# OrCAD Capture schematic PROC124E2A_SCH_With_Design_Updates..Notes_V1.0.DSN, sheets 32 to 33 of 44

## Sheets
32 31. PRU HEADER: size C; title: PRU HEADER
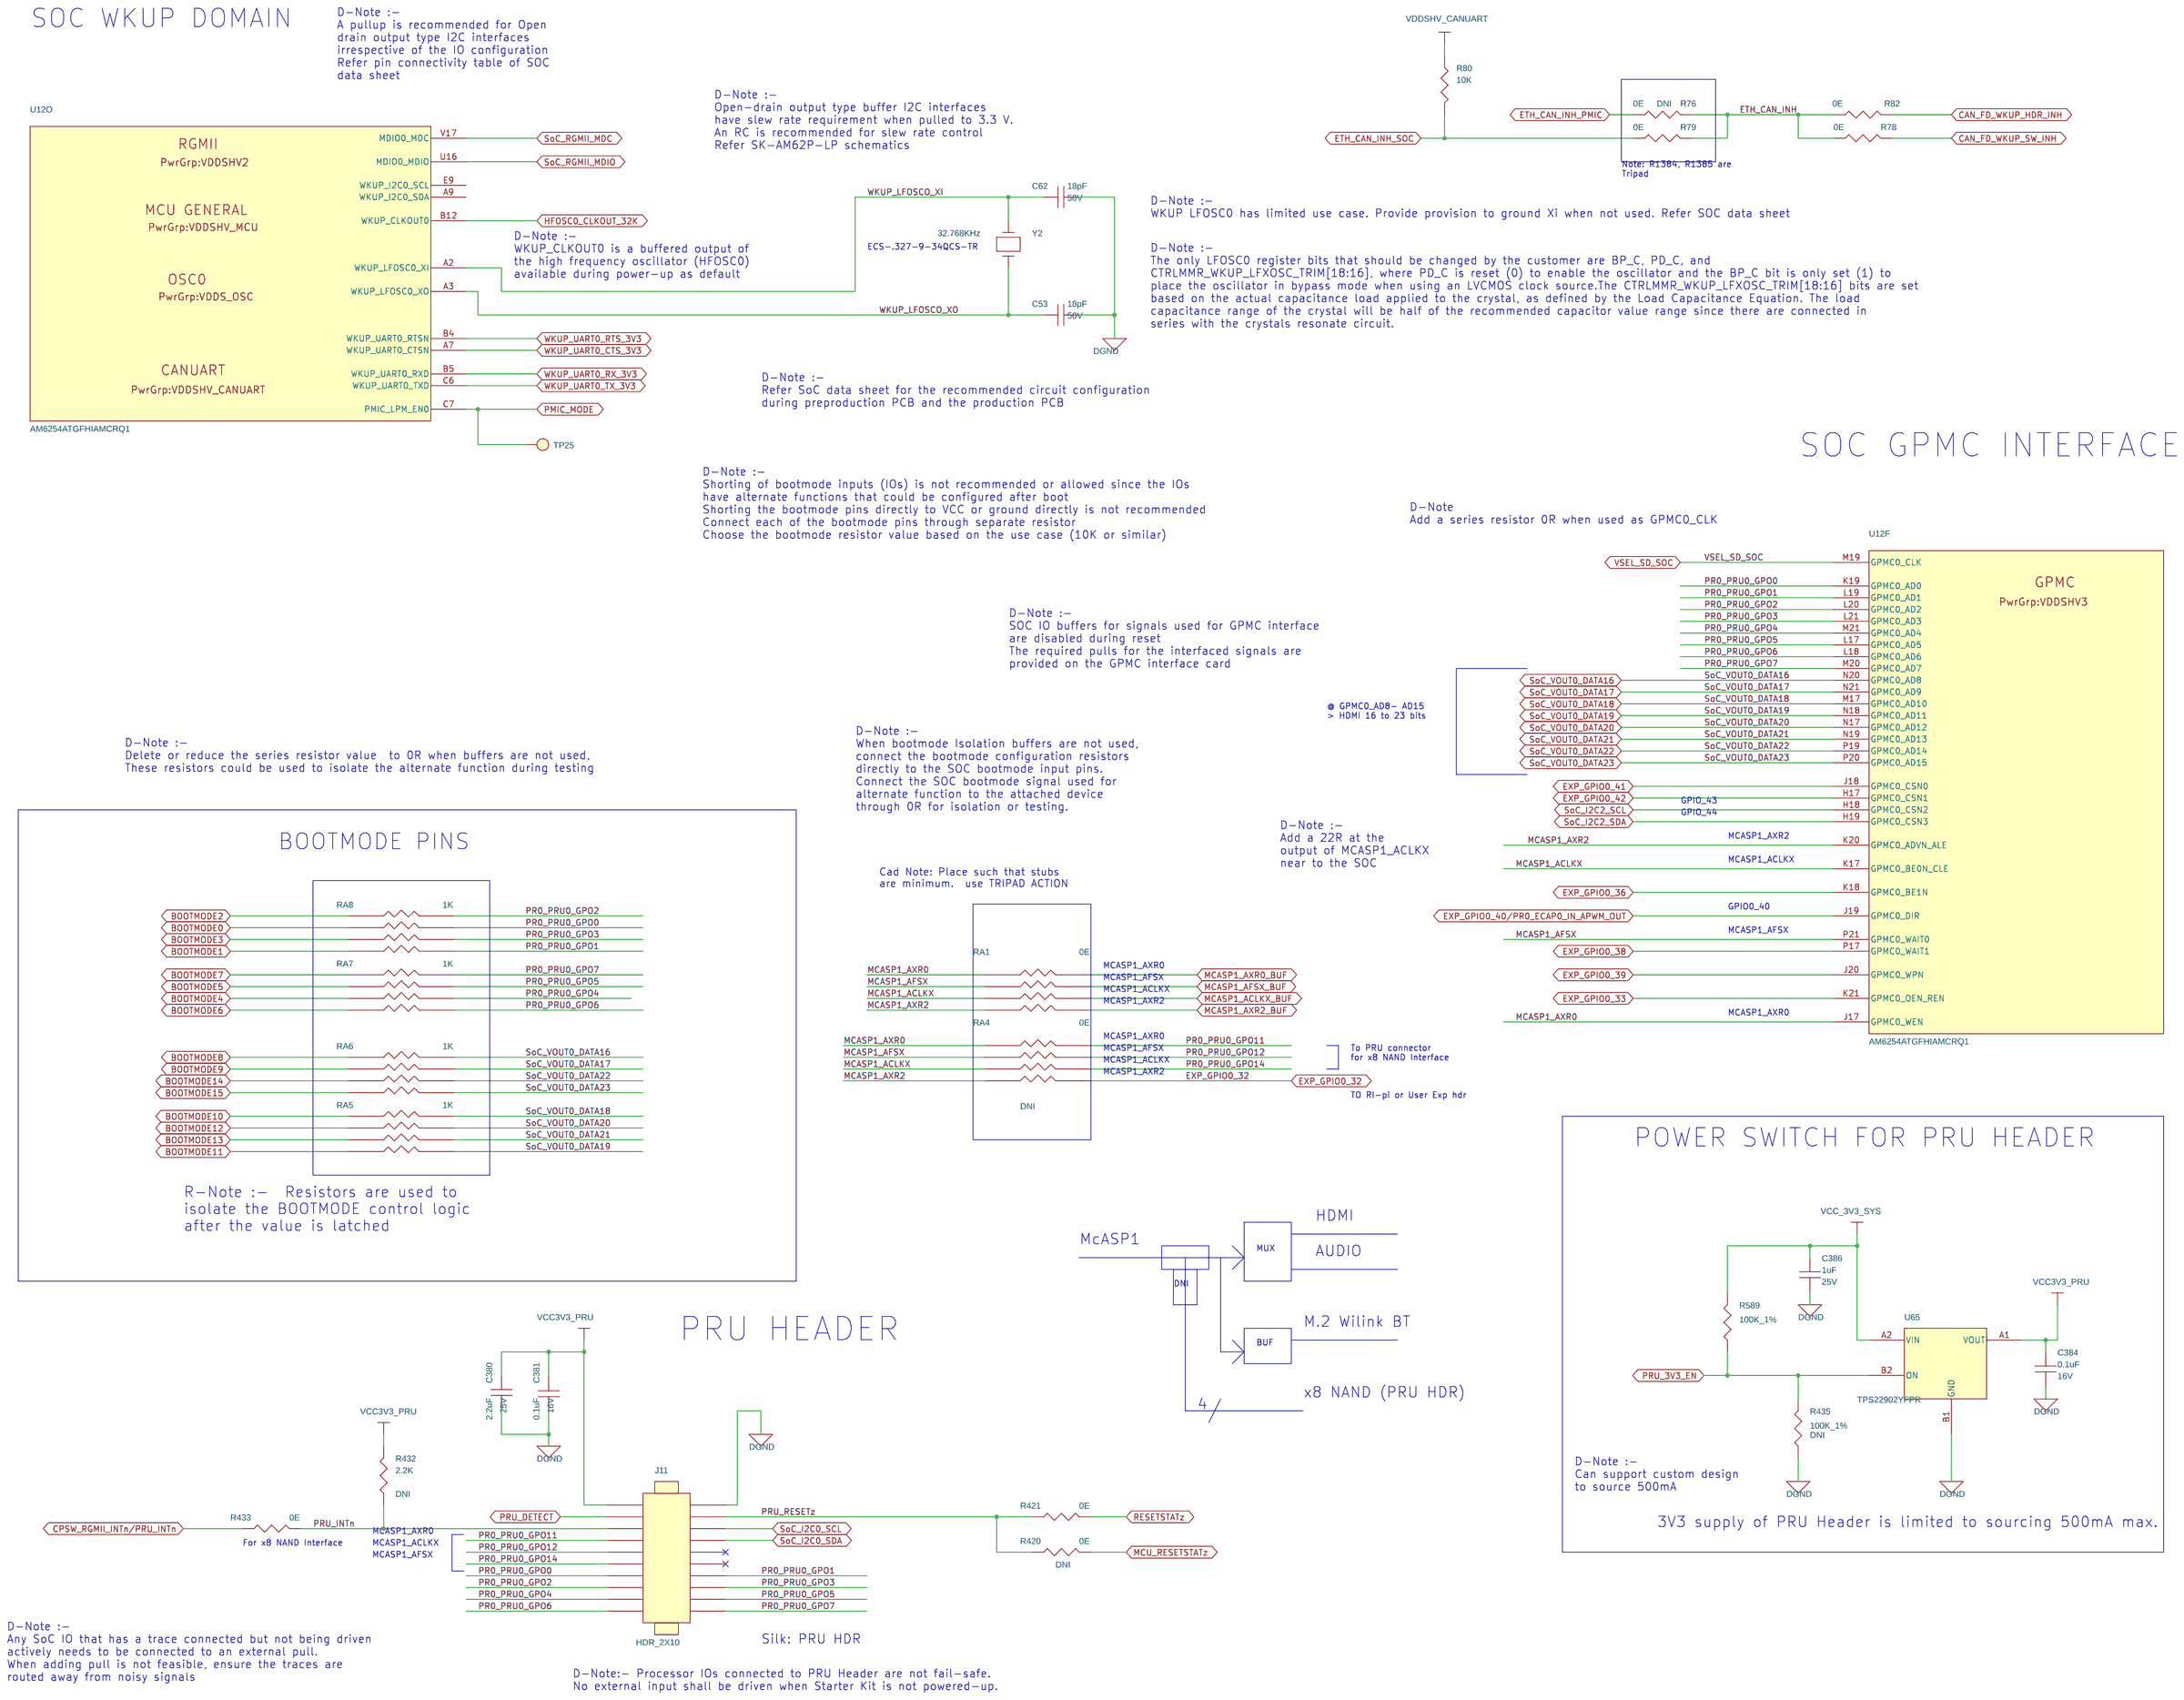
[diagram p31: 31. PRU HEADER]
33 32. USER EXPANSION CONNECTOR: size C; title: USER EXPANSION CONNECTOR
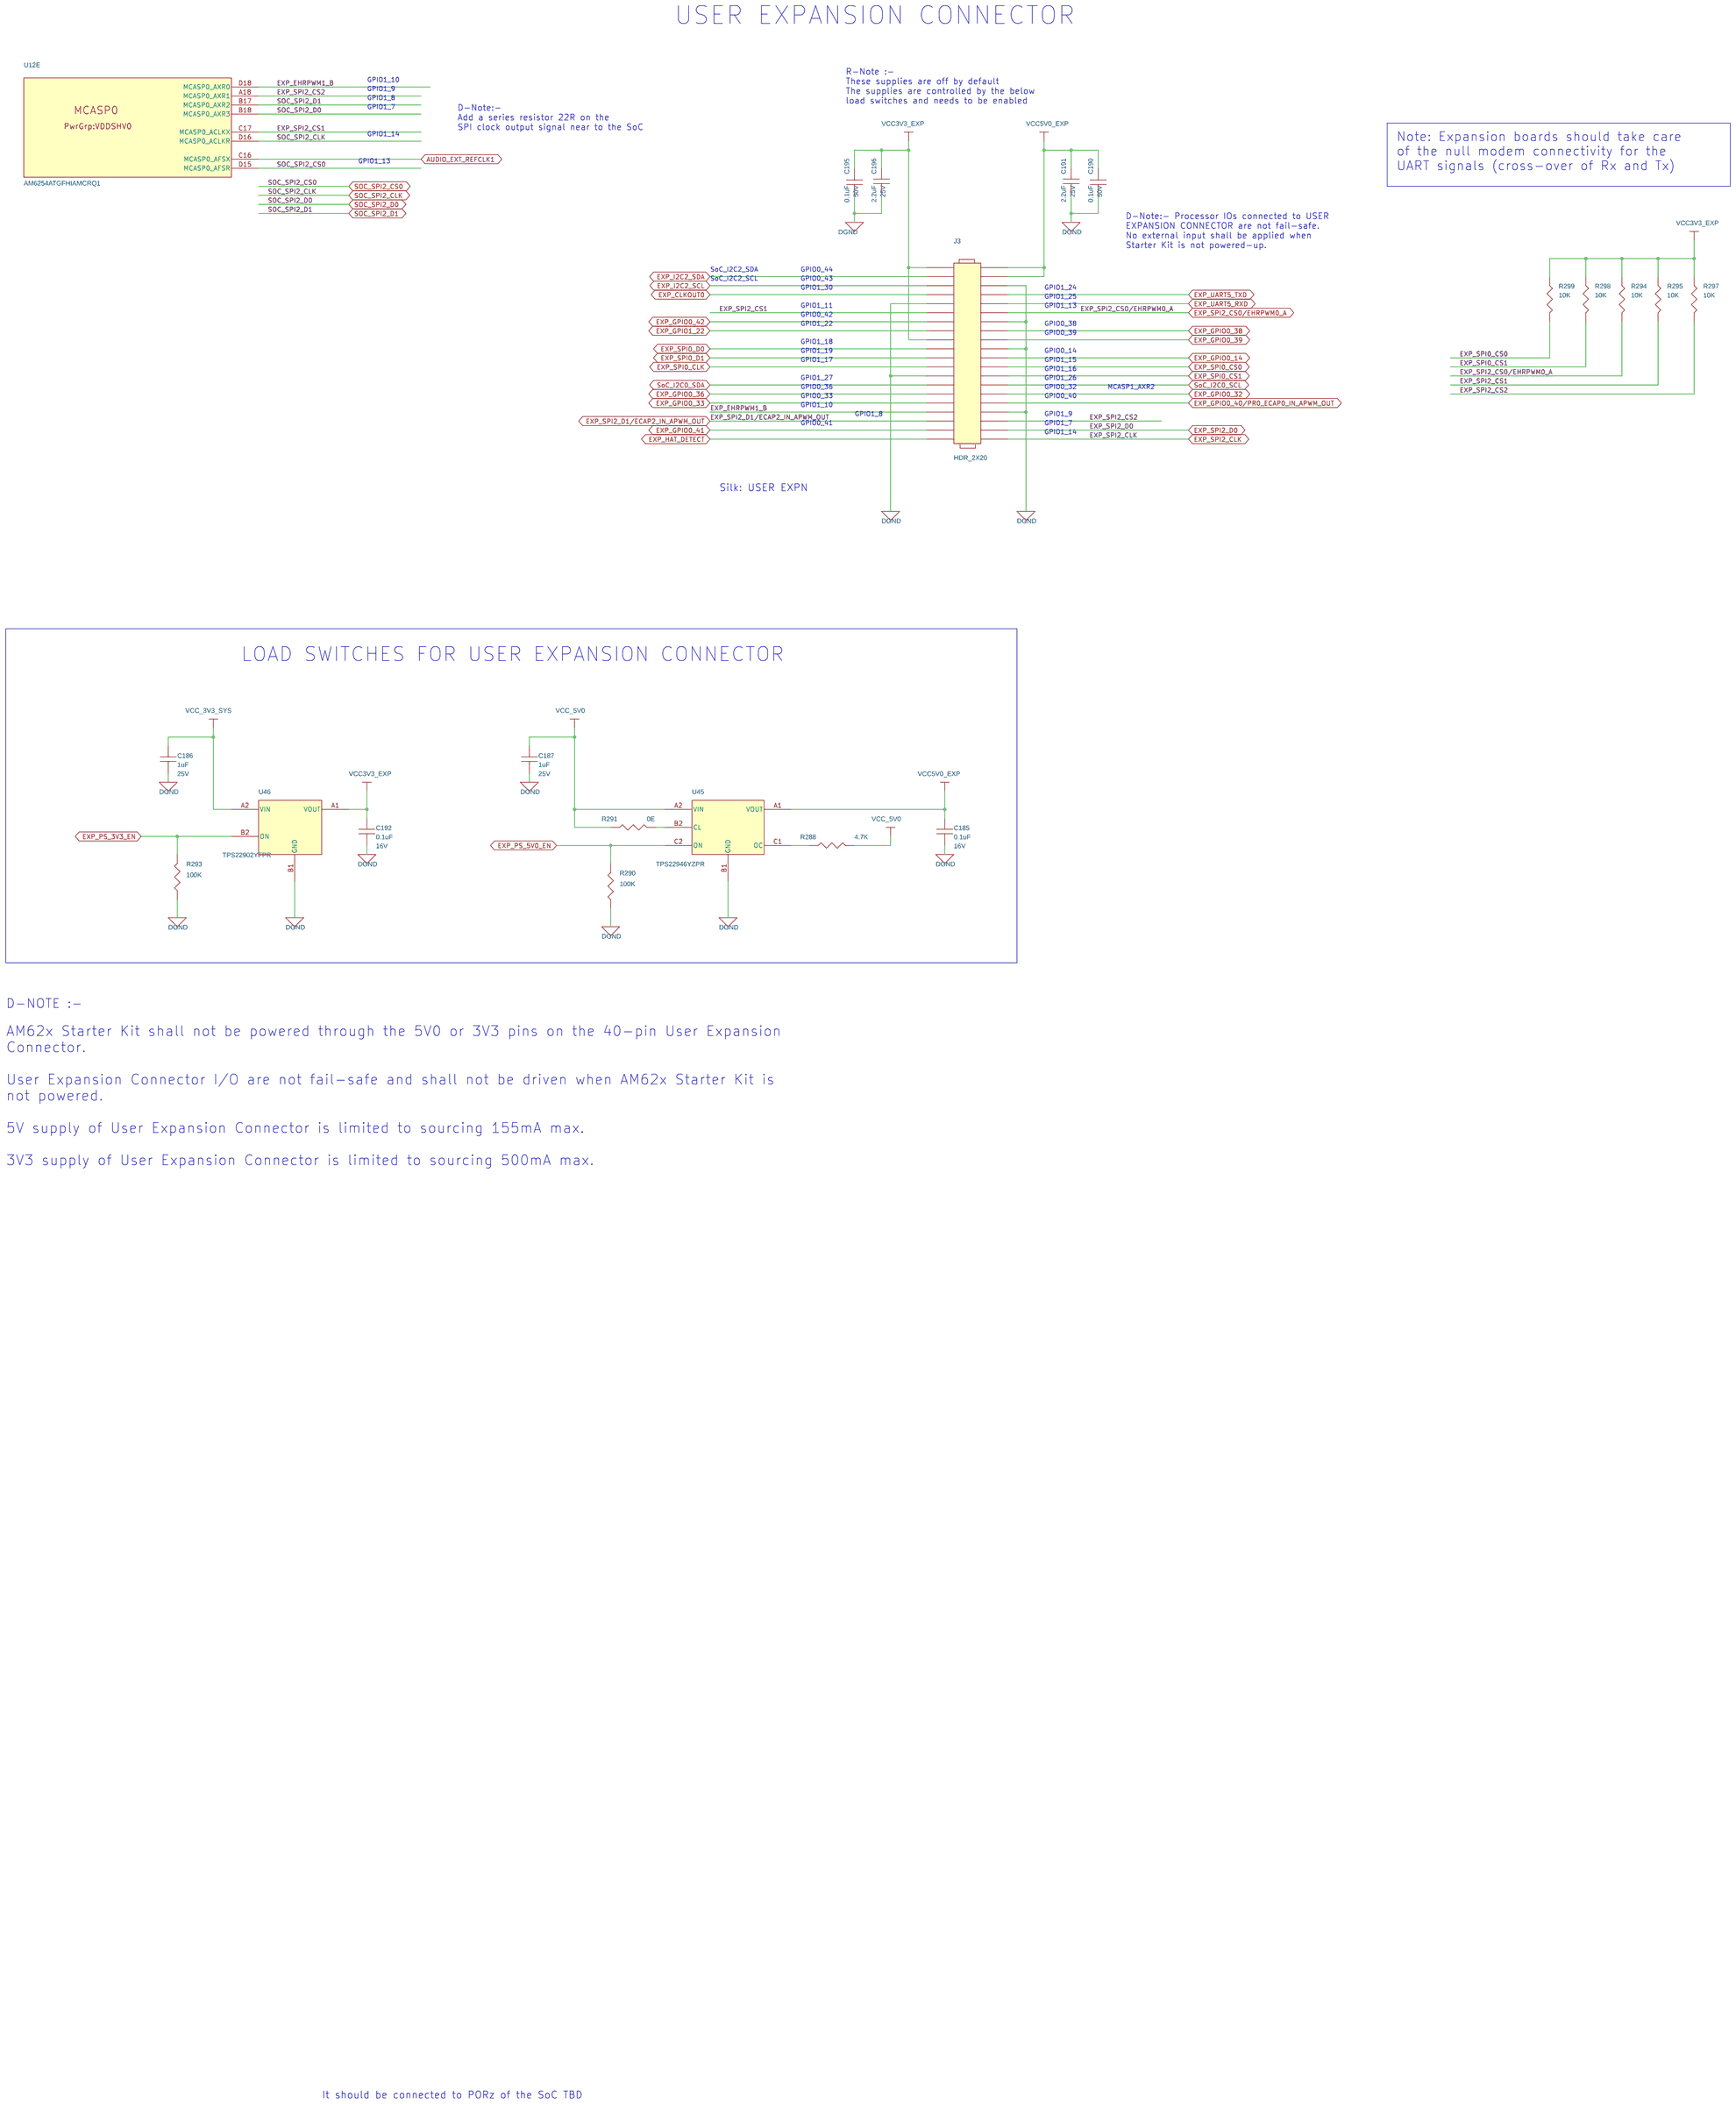
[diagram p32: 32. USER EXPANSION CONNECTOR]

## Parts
sheet 15. SOC POWER CAPS
U12  AM6254ATGFHIAMCRQ1  [FCBGA441_31-49_680X680_2-6]  (sections A,B,C,D,E,F,G,H,I,J,K,L,M,N,O,P,Q,R)
sheet 31. PRU HEADER
C53  18pF  [CAP0402_0-75]
C62  18pF  [CAP0402_0-75]
C380  2.2uF  [CAP0402_0-75]
C381  0.1uF  [CAP0201_0-5]
C384  0.1uF  [CAP0201_0-5]
C386  1uF  [CAP0402_0-75]
J11  HDR_2X10  [HDR_2X10_PREC010DAAN_S_T_8-4]
R76  0E  [RES0201_0-5]
R78  0E  [RES0201_0-5]
R79  0E  [RES0201_0-5]
R80  10K  [RES0201_0-5]
R82  0E  [RES0201_0-5]
R420  0E  [RES0201_0-5]
R421  0E  [RES0201_0-5]
R432  2.2K  [RES0201_0-5]
R433  0E  [RES0201_0-5]
R435  100K_1%  [RES0402_0-5]
R589  100K_1%  [RES0402_0-5]
RA1  0E  [RESA_EXB_0201-4_0-5]
RA4  0E  [RESA_EXB_0201-4_0-5]
RA5  1K  [RESA_EXB_0201-4_0-5]
RA6  1K  [RESA_EXB_0201-4_0-5]
RA7  1K  [RESA_EXB_0201-4_0-5]
RA8  1K  [RESA_EXB_0201-4_0-5]
TP25  TP20_SMD  [TP20_SMD]
U65  TPS22902YFPR  [DSBGA4_15-74_30X30_0-5]
Y2  32.768KHz  [XTAL_ECS-32_130X60_SMD_0-9]
sheet 32. USER EXPANSION CONNECTOR
C185  0.1uF  [CAP0201_0-5]
C186  1uF  [CAP0402_0-75]
C187  1uF  [CAP0402_0-75]
C190  0.1uF  [CAP0402_0-75]
C191  2.2uF  [CAP0402_0-75]
C192  0.1uF  [CAP0201_0-5]
C195  0.1uF  [CAP0402_0-75]
C196  2.2uF  [CAP0402_0-75]
J3  HDR_2X20  [HDR_2X20_PEC20DAAN_S_T_8-6]
R288  4.7K  [RES0201_0-5]
R290  100K  [RES0201_0-5]
R291  0E  [RES0201_0-5]
R293  100K  [RES0201_0-5]
R294  10K  [RES0201_0-5]
R295  10K  [RES0201_0-5]
R297  10K  [RES0201_0-5]
R298  10K  [RES0201_0-5]
R299  10K  [RES0201_0-5]
U45  TPS22946YZPR  [DSBGA6_19-68_40X60_0-5]
U46  TPS22902YFPR  [DSBGA4_15-74_30X30_0-5]

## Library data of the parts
U12 = AM6254ATGFHIAMCRQ1_FCBGA441: IC AM62Q SoC MICROPROCESSOR FCBGA441; Chkd/date: PRADEEP/180324; Crtd /date: TAMILARASU/180324; Custom_Duty: 15%; Customs_HS_Code: 85423100; Distributor_name: NA; Distributor_part_number: NA; Footprint Path: Y:\MIS_DATABASE\Library\ALTIUM_TOOL\PCB_FOOTPRINTS\Altium_Footprint_Lib.PcbLib; Height: 2.57MM; Library Path: Y:\MIS_DATABASE\Library\ALTIUM_TOOL\SCHEMATICS_PARTS\MS_MICROPROCESSOR_Library.schlib; Mfr_name: TEXAS INSTRUMENTS; Mistral Part No: 141224030001-R; Package: FCBGA441; Part_type: ICS\DIGITAL\MICROPROCESSOR; Project: TI_AM62Q_BRD; RoHS: NA; Temperature: NA; Tolerance: NA; Voltage: NA; Wattage: NA; Weight: NA; Datasheet: Y:\MIS_DATABASE\DATASHEETS\ICS\DIGITAL\MICROCONTROLLER\AM62Q-SoC.PDF
C53 C62 = CAP: CAP CERAMIC 18pF 50V 5% HI-Q C0G(NP0) 0402; Chkd/date: VASANTHA/030315; Crtd /date: NAVEED/271014; Custom_Duty: 15%; Customs_HS_Code: 85322990; Distributor_name: DIGIKEY; Distributor_part_number: 490-3119-1-ND; Footprint Path: Y:\MIS_DATABASE\Library\ALTIUM_TOOL\PCB_FOOTPRINTS\Altium_Footprint_Lib.PcbLib; Height: 0.55MM; Library Path: Y:\MIS_DATABASE\Library\ALTIUM_TOOL\SCHEMATICS_PARTS\MS_DISCRETE_Library.schlib; Mfr_name: MURATA; Mfr_part_number: GJM1555C1H180JB01D; Mistral Part No: 120014100019-R; Package: 0402; Part_type: CAPACITORS\CERAMIC; Project: DC_MIST_RDC; RoHS: RoHS; Temperature: -55°C+125°C; Tolerance: 5%; Voltage: 50V; Wattage: NA; Weight: 6mg; Datasheet: Y:\MIS_DATABASE\DATASHEETS\CAPACITORS\MURATA-GXX-SER_NOV17.PDF
C191 C196 C380 = CAP: CAP CERAMIC 2.2uF 25V 10% X5R 0402; Chkd/date: ALVY/010721; Crtd /date: MANIRAJA/010721; Custom_Duty: 15%; Customs_HS_Code: 85322990; Distributor_name: DIGIKEY; Distributor_part_number: 490-12703-1-ND; Footprint Path: Y:\MIS_DATABASE\Library\ALTIUM_TOOL\PCB_FOOTPRINTS\Altium_Footprint_Lib.PcbLib; Height: 0.70MM; Library Path: Y:\MIS_DATABASE\Library\ALTIUM_TOOL\SCHEMATICS_PARTS\MS_DISCRETE_Library.schlib; Mfr_name: MURATA; Mfr_part_number: GRM155R61E225KE11D; Mistral Part No: 120015120001-R; Package: 0402; Part_type: CAPACITORS\CERAMIC; Project: TI_AM263X_CC; RoHS: RoHS; Temperature: -55°C+85°C; Tolerance: 10%; Voltage: 25V; Wattage: NA; Weight: 1.5mg; Datasheet: Y:\MIS_DATABASE\DATASHEETS\CAPACITORS\GRM155R61E225KE11.PDF
C381 = CAP: CAP CERAMIC 0.1uF 16V 10% X5R 0201; Alt_Mfr_name: YAGEO AMERICA; Alt_Mfr_part_number: CC0402KRX5R8BB104; Chkd/date: MANIRAJA/230118; Crtd /date: MANIRAJA/230118; Custom_Duty: 15%; Customs_HS_Code: 85322990; Distributor_name: DIGIKEY; Distributor_part_number: 490-14305-1-ND; Footprint Path: Y:\MIS_DATABASE\Library\ALTIUM_TOOL\PCB_FOOTPRINTS\Altium_Footprint_Lib.PcbLib; Height: 0.33MM; Library Path: Y:\MIS_DATABASE\Library\ALTIUM_TOOL\SCHEMATICS_PARTS\MS_DISCRETE_Library.schlib; Mfr_name: MURATA; Mfr_part_number: GRM033R61C104KE14D; Mistral Part No: 120009030072-R; Package: 0201; Part_type: CAPACITORS\CERAMIC; Project: TI_MAXIE_CPB; RoHS: RoHS; Temperature: -55°C+85°C; Tolerance: 10%; Voltage: 16V; Wattage: NA; Weight: 0.33mg; Datasheet: Y:\MIS_DATABASE\DATASHEETS\CAPACITORS\GRM033R61C104KE14.PDF
C384 = CAP: CAP CERAMIC 0.1uF 16V 10% X5R 0201; Chkd/date: PRADEEP/130623; Crtd /date: PRADEEP/130623; Custom_Duty: 15%; Customs_HS_Code: 85322990; Distributor_name: NA; Distributor_part_number: NA; Footprint Path: Y:\MIS_DATABASE\Library\ALTIUM_TOOL\PCB_FOOTPRINTS\Altium_Footprint_Lib.PcbLib; Height: 0.33MM; Library Path: Y:\MIS_DATABASE\Library\ALTIUM_TOOL\SCHEMATICS_PARTS\MS_DISCRETE_Library.schlib; Mfr_name: MURATA; Mfr_part_number: GRT033R61C104KE01; Mistral Part No: 120022060019-R; Package: 0201; Part_type: CAPACITORS\CERAMIC; Project: AM62P_SK; RoHS: RoHS; Temperature: -55°C+85°C; Tolerance: 10%; Voltage: 16V; Wattage: NA; Weight: 0.33mg; Datasheet: Y:\MIS_DATABASE\DATASHEETS\CAPACITORS\GRT033R61C104KE01XX.PDF
C186 C187 C386 = CAP: CAP CERAMIC 1uF 25V 10% X6S 0402; Chkd/date: MANIRAJA/140518; Crtd /date: ALVY/140518; Custom_Duty: 15%; Customs_HS_Code: 85322990; Distributor_name: DIGIKEY; Distributor_part_number: 490-10014-1-ND; Footprint Path: Y:\MIS_DATABASE\Library\ALTIUM_TOOL\PCB_FOOTPRINTS\Altium_Footprint_Lib.PcbLib; Height: 0.60MM; Library Path: Y:\MIS_DATABASE\Library\ALTIUM_TOOL\SCHEMATICS_PARTS\MS_DISCRETE_Library.schlib; Mfr_name: MURATA; Mfr_part_number: GRM155C81E105KE11D; Mistral Part No: 120018050004-R; Package: 0402; Part_type: CAPACITORS\CERAMIC; Project: TI_SVB_MAXWELL_DUT; RoHS: RoHS; Temperature: -55°C+105°C; Tolerance: 10%; Voltage: 25V; Wattage: NA; Weight: 6mg; Datasheet: Y:\MIS_DATABASE\DATASHEETS\CAPACITORS\GRM155C81E105KE11X.PDF
J11 = HEADER_10X2: CON HDR 2X10 2.54MM PITCH ST TH; Chkd/date: MANIRAJA/270721; Crtd /date: ALVY/260721; Custom_Duty: 24%; Customs_HS_Code: 85369090; Distributor_name: DIGIKEY; Distributor_part_number: S2012EC-10-ND; Footprint Path: Y:\MIS_DATABASE\Library\ALTIUM_TOOL\PCB_FOOTPRINTS\Altium_Footprint_Lib.PcbLib; Height: 8.34MM; Library Path: Y:\MIS_DATABASE\Library\ALTIUM_TOOL\SCHEMATICS_PARTS\MS_CONNECTOR_Library.schlib; Mfr_name: SULLINS CONNECTOR; Mfr_part_number: PREC010DAAN-RC; Mistral Part No: 150021070022-R; Package: THRU-HOLE; Part_type: CONNECTOR\HEADERS; Project: TI_AM335x SK_BRD; RoHS: RoHS; Temperature: -40°C+105°C; Tolerance: NA; Voltage: NA; Wattage: NA; Weight: NA; Datasheet: Y:\MIS_DATABASE\DATASHEETS\CONNECTORS\PRPCXXDXXN-SER.PDF
R76 = RESISTOR: RES 0E 1/20W 5% 0201; Assembly_Instruction: DNI; Chkd/date: NAVEED/301214; Crtd /date: MUDDU/120710; Custom_Duty: 15%; Customs_HS_Code: 85332119; Distributor_name: DIGIKEY; Distributor_part_number: 311-0.0NCT-ND; Footprint Path: Y:\MIS_DATABASE\Library\ALTIUM_TOOL\PCB_FOOTPRINTS\Altium_Footprint_Lib.PcbLib; Height: 0.26MM; Library Path: Y:\MIS_DATABASE\Library\ALTIUM_TOOL\SCHEMATICS_PARTS\MS_DISCRETE_Library.schlib; Manufacturer: YAGEO AMERICA; Mfr_name: YAGEO AMERICA; Mfr_part_number: RC0201JR-070RL; Mistral Part No: 110010070067-R; Package: 0201; Part_type: RESISTORS\FIXED; Project: PB_BUGBASE; RoHS: RoHS; Temperature: -55°C+125°C; Tolerance: 5%; Voltage: NA; Wattage: 1/20W; Weight: 0.17mg; Datasheet: Y:\MIS_DATABASE\DATASHEETS\RESISTORS\RCXXXXL-SER_MAR18.PDF
R78 = RESISTOR: RES 0E 1/20W 5% 0201; Chkd/date: NAVEED/301214; Crtd /date: MUDDU/120710; Custom_Duty: 15%; Customs_HS_Code: 85332119; Distributor_name: DIGIKEY; Distributor_part_number: 311-0.0NCT-ND; Footprint Path: Y:\MIS_DATABASE\Library\ALTIUM_TOOL\PCB_FOOTPRINTS\Altium_Footprint_Lib.PcbLib; Height: 0.26MM; Library Path: Y:\MIS_DATABASE\Library\ALTIUM_TOOL\SCHEMATICS_PARTS\MS_DISCRETE_Library.schlib; Manufacturer: YAGEO AMERICA; Mfr_name: YAGEO AMERICA; Mfr_part_number: RC0201JR-070RL; Mistral Part No: 110010070067-R; Package: 0201; Part_type: RESISTORS\FIXED; Project: PB_BUGBASE; RoHS: RoHS; Temperature: -55°C+125°C; Tolerance: 5%; Voltage: NA; Wattage: 1/20W; Weight: 0.17mg; Datasheet: Y:\MIS_DATABASE\DATASHEETS\RESISTORS\RCXXXXL-SER_MAR18.PDF
R79 R82 R291 R421 R433 = RESISTOR: RES 0E 1/20W 5% 0201; Chkd/date: NAVEED/301214; Crtd /date: MUDDU/120710; Custom_Duty: 15%; Customs_HS_Code: 85332119; Distributor_name: DIGIKEY; Distributor_part_number: 311-0.0NCT-ND; Footprint Path: Y:\MIS_DATABASE\Library\ALTIUM_TOOL\PCB_FOOTPRINTS\Altium_Footprint_Lib.PcbLib; Height: 0.26MM; Library Path: Y:\MIS_DATABASE\Library\ALTIUM_TOOL\SCHEMATICS_PARTS\MS_DISCRETE_Library.schlib; Mfr_name: YAGEO AMERICA; Mfr_part_number: RC0201JR-070RL; Mistral Part No: 110010070067-R; Package: 0201; Part_type: RESISTORS\FIXED; Project: PB_BUGBASE; RoHS: RoHS; Temperature: -55°C+125°C; Tolerance: 5%; Voltage: NA; Wattage: 1/20W; Weight: 0.17mg; Datasheet: Y:\MIS_DATABASE\DATASHEETS\RESISTORS\RCXXXXL-SER_MAR18.PDF
R80 R294 R295 R297-R299 = RESISTOR: RES 10K 1/20W 5% 0201; Chkd/date: MANIRAJA/050517; Crtd /date: MANIRAJA/050517; Custom_Duty: 15%; Customs_HS_Code: 85332119; Distributor_name: DIGIKEY; Distributor_part_number: 311-10KNCT-ND; Footprint Path: Y:\MIS_DATABASE\Library\ALTIUM_TOOL\PCB_FOOTPRINTS\Altium_Footprint_Lib.PcbLib; Height: 0.26MM; Library Path: Y:\MIS_DATABASE\Library\ALTIUM_TOOL\SCHEMATICS_PARTS\MS_DISCRETE_Library.schlib; Mfr_name: YAGEO AMERICA; Mfr_part_number: RC0201JR-0710KL; Mistral Part No: 110010070051-R; Package: 0201; Part_type: RESISTORS\FIXED; Project: GOLDEN-I LITE; RoHS: RoHS; Temperature: -55°C+125°C; Tolerance: 5%; Voltage: NA; Wattage: 1/20W; Weight: 0.17mg; Datasheet: Y:\MIS_DATABASE\DATASHEETS\RESISTORS\RCXXXXL-SER_MAR18.PDF
R420 = RESISTOR: RES 0E 1/20W 5% 0201; Assembly_Instruction: DNI; Chkd/date: NAVEED/301214; Crtd /date: MUDDU/120710; Custom_Duty: 15%; Customs_HS_Code: 85332119; Distributor_name: DIGIKEY; Distributor_part_number: 311-0.0NCT-ND; Footprint Path: Y:\MIS_DATABASE\Library\ALTIUM_TOOL\PCB_FOOTPRINTS\Altium_Footprint_Lib.PcbLib; Height: 0.26MM; Library Path: Y:\MIS_DATABASE\Library\ALTIUM_TOOL\SCHEMATICS_PARTS\MS_DISCRETE_Library.schlib; Mfr_name: YAGEO AMERICA; Mfr_part_number: RC0201JR-070RL; Mistral Part No: 110010070067-R; Package: 0201; Part_type: RESISTORS\FIXED; Project: PB_BUGBASE; RoHS: RoHS; Temperature: -55°C+125°C; Tolerance: 5%; Voltage: NA; Wattage: 1/20W; Weight: 0.17mg; Datasheet: Y:\MIS_DATABASE\DATASHEETS\RESISTORS\RCXXXXL-SER_MAR18.PDF
R432 = RESISTOR: RES 2.2K 1/20W 5% 0201; Assembly_Instruction: DNI; Chkd/date: MANIRAJA/310821; Crtd /date: ALVY/310821; Custom_Duty: 15%; Customs_HS_Code: 85332119; Distributor_name: DIGIKEY; Distributor_part_number: P123277CT-ND; Footprint Path: Y:\MIS_DATABASE\Library\ALTIUM_TOOL\PCB_FOOTPRINTS\Altium_Footprint_Lib.PcbLib; Height: 0.26MM; Library Path: Y:\MIS_DATABASE\Library\ALTIUM_TOOL\SCHEMATICS_PARTS\MS_DISCRETE_Library.schlib; Mfr_name: PANASONIC-ECG; Mfr_part_number: ERJ-1GNJ222C; Mistral Part No: 110009030427-R; Package: 0201; Part_type: RESISTORS\FIXED; Project: TI_AM335x SK_BRD; RoHS: RoHS; Temperature: -55°C+125°C; Tolerance: 5%; Voltage: NA; Wattage: 1/20W; Weight: 0.15mg; Datasheet: Y:\MIS_DATABASE\DATASHEETS\RESISTORS\PAN-ERJSER_NOV17.PDF
R435 = RESISTOR: RES 100K 1/10W 1% 0402; Assembly_Instruction: DNI; Chkd/date: VASANTHA/201216; Crtd /date: MAZHAR/130306; Custom_Duty: 15%; Customs_HS_Code: 85332119; Distributor_name: DIGIKEY; Distributor_part_number: P100KLCT-ND; Footprint Path: Y:\MIS_DATABASE\Library\ALTIUM_TOOL\PCB_FOOTPRINTS\Altium_Footprint_Lib.PcbLib; Height: 0.40MM; Library Path: Y:\MIS_DATABASE\Library\ALTIUM_TOOL\SCHEMATICS_PARTS\MS_DISCRETE_Library.schlib; Mfr_name: PANASONIC-ECG; Mfr_part_number: ERJ-2RKF1003X; Mistral Part No: 110009030187-R; Package: 0402; Part_type: RESISTORS\FIXED; Project: J32; RoHS: RoHS; Temperature: -55°C+155°C; Tolerance: 1%; Voltage: NA; Wattage: 1/10W; Weight: 0.8mg; Datasheet: Y:\MIS_DATABASE\DATASHEETS\RESISTORS\PAN-ERJSER_NOV17.PDF
R589 = RESISTOR: RES 100K 1/10W 1% 0402; Chkd/date: VASANTHA/201216; Crtd /date: MAZHAR/130306; Custom_Duty: 15%; Customs_HS_Code: 85332119; Distributor_name: DIGIKEY; Distributor_part_number: P100KLCT-ND; Footprint Path: Y:\MIS_DATABASE\Library\ALTIUM_TOOL\PCB_FOOTPRINTS\Altium_Footprint_Lib.PcbLib; Height: 0.40MM; Library Path: Y:\MIS_DATABASE\Library\ALTIUM_TOOL\SCHEMATICS_PARTS\MS_DISCRETE_Library.schlib; Mfr_name: PANASONIC-ECG; Mfr_part_number: ERJ-2RKF1003X; Mistral Part No: 110009030187-R; Package: 0402; Part_type: RESISTORS\FIXED; Project: J32; RoHS: RoHS; Temperature: -55°C+155°C; Tolerance: 1%; Voltage: NA; Wattage: 1/10W; Weight: 0.8mg; Datasheet: Y:\MIS_DATABASE\DATASHEETS\RESISTORS\PAN-ERJSER_NOV17.PDF
RA1 = RESARR_ISO4: RES ARRAY 0E 31mW JUMPER 0201-4; Chkd/date: MANIRAJA/290918; Crtd /date: MANIRAJA/290918; Custom_Duty: 15%; Customs_HS_Code: 85332119; Distributor_name: DIGIKEY; Distributor_part_number: Y6000CT-ND; Footprint Path: Y:\MIS_DATABASE\Library\ALTIUM_TOOL\PCB_FOOTPRINTS\Altium_Footprint_Lib.PcbLib; Height: 0.45MM; Library Path: Y:\MIS_DATABASE\Library\ALTIUM_TOOL\SCHEMATICS_PARTS\MS_DISCRETE_Library.schlib; Manufacturer: PANASONIC-ECG; Mfr_name: PANASONIC-ECG; Mfr_part_number: EXB-18VR000X; Mistral Part No: 110018090033-R; Package: 0201-4; Part_type: RESISTORS\ARRAY; Project: TI_60GHz-AOP; RoHS: RoHS; Temperature: -55°C+125°C; Tolerance: NA; Voltage: NA; Wattage: 31mW; Weight: 1mg; Datasheet: Y:\MIS_DATABASE\DATASHEETS\RESISTORS\EXB-18V.PDF
RA4 = RESARR_ISO4: RES ARRAY 0E 31mW JUMPER 0201-4; Assembly_Instruction: DNI; Chkd/date: MANIRAJA/290918; Crtd /date: MANIRAJA/290918; Custom_Duty: 15%; Customs_HS_Code: 85332119; Distributor_name: DIGIKEY; Distributor_part_number: Y6000CT-ND; Footprint Path: Y:\MIS_DATABASE\Library\ALTIUM_TOOL\PCB_FOOTPRINTS\Altium_Footprint_Lib.PcbLib; Height: 0.45MM; Library Path: Y:\MIS_DATABASE\Library\ALTIUM_TOOL\SCHEMATICS_PARTS\MS_DISCRETE_Library.schlib; Manufacturer: PANASONIC-ECG; Mfr_name: PANASONIC-ECG; Mfr_part_number: EXB-18VR000X; Mistral Part No: 110018090033-R; Package: 0201-4; Part_type: RESISTORS\ARRAY; Project: TI_60GHz-AOP; RoHS: RoHS; Temperature: -55°C+125°C; Tolerance: NA; Voltage: NA; Wattage: 31mW; Weight: 1mg; Datasheet: Y:\MIS_DATABASE\DATASHEETS\RESISTORS\EXB-18V.PDF
RA5-RA8 = RESARR_ISO4: RES ARRAY 1K 31mW 5% 0201-4; Chkd/date: NAVEED/110515; Crtd /date: VASANTHA/080515; Custom_Duty: 15%; Customs_HS_Code: 85332119; Distributor_name: DIGIKEY; Distributor_part_number: Y6102CT-ND; Footprint Path: Y:\MIS_DATABASE\Library\ALTIUM_TOOL\PCB_FOOTPRINTS\Altium_Footprint_Lib.PcbLib; Height: 0.45MM; Library Path: Y:\MIS_DATABASE\Library\ALTIUM_TOOL\SCHEMATICS_PARTS\MS_DISCRETE_Library.schlib; Mfr_name: PANASONIC-ECG; Mfr_part_number: EXB-18V102JX; Mistral Part No: 110015050003-R; Package: 0201-4; Part_type: RESISTORS\ARRAY; Project: FREE SCALE NANO; RoHS: RoHS; Temperature: -55°C+125°C; Tolerance: 5%; Voltage: NA; Wattage: 31mW; Weight: 1mg; Datasheet: Y:\MIS_DATABASE\DATASHEETS\RESISTORS\EXB-18V.PDF
TP25 = TESTPOINT: TESTPOINT CIR 20 SMD; Chkd/date: SHREESHAIL/171006; Crtd /date: MAZHAR/171006; Custom_Duty: NA; Customs_HS_Code: NA; Distributor_name: NA; Distributor_part_number: NA; Footprint Path: Y:\MIS_DATABASE\Library\ALTIUM_TOOL\PCB_FOOTPRINTS\Altium_Footprint_Lib.PcbLib; Height: NA; Library Path: Y:\MIS_DATABASE\Library\ALTIUM_TOOL\SCHEMATICS_PARTS\MS_DISCRETE_Library.schlib; MECHANICAL 3D STEP FILE: NA; Mfr_name: LOCAL; Mistral Part No: NA; Package: SMD; Project: BT MODULE_CSRBC04; RoHS: NA; Temperature: NA; Tolerance: NA; Voltage: NA; Wattage: NA; Weight: NA; Datasheet: NA
U46 U65 = TPS22912CYZVR_DSBGA4: IC 3.6V 500mA 78mE ON-RESISTANCE LOAD SWITCH WITH CONTROLLED TURNON DSBGA4; Chkd/date: MANIRAJA/170920; Crtd /date: ALVY/160920; Custom_Duty: 15%; Customs_HS_Code: 85423100; Distributor_name: DIGIKEY; Distributor_part_number: 296-24472-1-ND; Footprint Path: Y:\MIS_DATABASE\Library\ALTIUM_TOOL\PCB_FOOTPRINTS\Altium_Footprint_Lib.PcbLib; Height: 0.50MM; Library Path: Y:\MIS_DATABASE\Library\ALTIUM_TOOL\SCHEMATICS_PARTS\MS_MISCPOWER_Library.schlib; Mfr_name: TEXAS INSTRUMENTS; Mistral Part No: 142020090007-R; Package: DSBGA4; Part_type: ICS\POWER; Project: AM64X_SKEVM; RoHS: RoHS; Temperature: -40°C+85°C; Tolerance: NA; Voltage: NA; Wattage: NA; Weight: 0.7mg; Datasheet: Y:\MIS_DATABASE\DATASHEETS\ICS\POWER\TPS22901-2-3.PDF
Y2 = CRY: CRY 32.768KHz 9pF SMD; Chkd/date: VASANTHA/090419; Crtd /date: ALVY/090419; Custom_Duty: 24%; Customs_HS_Code: 85439000; Distributor_name: DIGIKEY; Distributor_part_number: XC2160CT-ND; Footprint Path: Y:\MIS_DATABASE\Library\ALTIUM_TOOL\PCB_FOOTPRINTS\Altium_Footprint_Lib.PcbLib; Height: 0.90MM; Library Path: Y:\MIS_DATABASE\Library\ALTIUM_TOOL\SCHEMATICS_PARTS\MS_DISCRETE_Library.schlib; Mfr_name: ECS INC; Mfr_part_number: ECS-.327-9-34QCS-TR; Mistral Part No: 130019040003-R; Package: SMD; Part_type: CRYSTAL; Project: J7ES_SOM_DUAL-LEO_PMIC; RoHS: RoHS; Temperature: -40°C+125°C; Tolerance: NA; Voltage: NA; Wattage: NA; Weight: 16mg; Datasheet: Y:\MIS_DATABASE\DATASHEETS\MISC\CRY_OSC\ECS-34Q.PDF
C185 C192 = CAP: CAP CERAMIC 0.1uF 16V 10% X5R 0201; Chkd/date: MANIRAJA/230118; Crtd /date: MANIRAJA/230118; Custom_Duty: 15%; Customs_HS_Code: 85322990; Distributor_name: DIGIKEY; Distributor_part_number: 490-14305-1-ND; Footprint Path: Y:\MIS_DATABASE\Library\ALTIUM_TOOL\PCB_FOOTPRINTS\Altium_Footprint_Lib.PcbLib; Height: 0.33MM; Library Path: Y:\MIS_DATABASE\Library\ALTIUM_TOOL\SCHEMATICS_PARTS\MS_DISCRETE_Library.schlib; Mfr_name: MURATA; Mfr_part_number: GRM033R61C104KE14D; Mistral Part No: 120009030072-R; Package: 0201; Part_type: CAPACITORS\CERAMIC; Project: TI_MAXIE_CPB; RoHS: RoHS; Temperature: -55°C+85°C; Tolerance: 10%; Voltage: 16V; Wattage: NA; Weight: 0.33mg; Datasheet: Y:\MIS_DATABASE\DATASHEETS\CAPACITORS\GRM033R61C104KE14.PDF
C190 C195 = CAP: CAP CERAMIC 0.1uF 50V 10% X7R 0402; Alt_Mfr_name: YAGEO AMERICA; Alt_Mfr_part_number: CC0402KRX5R8BB104; Chkd/date: MANIRAJA/261020; Crtd /date: ALVY/211020; Custom_Duty: 15%; Customs_HS_Code: 85322990; Distributor_name: DIGIKEY; Distributor_part_number: 490-10700-1-ND; Footprint Path: Y:\MIS_DATABASE\Library\ALTIUM_TOOL\PCB_FOOTPRINTS\Altium_Footprint_Lib.PcbLib; Height: 0.55MM; Library Path: Y:\MIS_DATABASE\Library\ALTIUM_TOOL\SCHEMATICS_PARTS\MS_DISCRETE_Library.schlib; Mfr_name: MURATA; Mfr_part_number: GRM155R71H104KE14D; Mistral Part No: 120011100014-R; Package: 0402; Part_type: CAPACITORS\CERAMIC; Project: J7_CP; RoHS: RoHS; Temperature: -55°C+125°C; Tolerance: 10%; Voltage: 50V; Wattage: NA; Weight: 3.1mg; Datasheet: Y:\MIS_DATABASE\DATASHEETS\CAPACITORS\GRM155R71H104KE14.PDF
J3 = HEADER_20X2: CON HDR 2X20 2.54MM PITCH ST TH; Chkd/date: MANIRAJA/261020; Crtd /date: MANIRAJA/261020; Custom_Duty: 24%; Customs_HS_Code: 85369090; Distributor_name: DIGIKEY; Distributor_part_number: S2012E-20-ND; Footprint Path: Y:\MIS_DATABASE\Library\ALTIUM_TOOL\PCB_FOOTPRINTS\Altium_Footprint_Lib.PcbLib; Height: 8.58MM; Library Path: Y:\MIS_DATABASE\Library\ALTIUM_TOOL\SCHEMATICS_PARTS\MS_CONNECTOR_Library.schlib; Mfr_name: SULLINS CONNECTOR; Mfr_part_number: PEC20DAAN; Mistral Part No: 150020100013-R; Package: THRU-HOLE; Part_type: CONNECTOR\HEADERS; Project: AM64X_SKEVM; RoHS: RoHS; Temperature: -65°C+125°C; Tolerance: NA; Voltage: NA; Wattage: NA; Weight: NA; Datasheet: Y:\MIS_DATABASE\DATASHEETS\CONNECTORS\XXCXXDXXN.PDF
R288 = RESISTOR: RES 4.7K 1/20W 5% 0201; Chkd/date: MANIRAJA/200921; Crtd /date: ALVY/200921; Custom_Duty: 15%; Customs_HS_Code: 85332119; Distributor_name: DIGIKEY; Distributor_part_number: 311-4.7KNCT-ND; Footprint Path: Y:\MIS_DATABASE\Library\ALTIUM_TOOL\PCB_FOOTPRINTS\Altium_Footprint_Lib.PcbLib; Height: 0.26MM; Library Path: Y:\MIS_DATABASE\Library\ALTIUM_TOOL\SCHEMATICS_PARTS\MS_DISCRETE_Library.schlib; Mfr_name: YAGEO AMERICA; Mfr_part_number: RC0201JR-074K7L; Mistral Part No: 110021090007-R; Package: 0201; Part_type: RESISTORS\FIXED; Project: TI_AM62x SKEVM_BRD; RoHS: RoHS; Temperature: -55°C+125°C; Tolerance: 5%; Voltage: NA; Wattage: 1/20W; Weight: 0.17mg; Datasheet: Y:\MIS_DATABASE\DATASHEETS\RESISTORS\RCXXXXL-SER_MAR18.PDF
R290 R293 = RESISTOR: RES 100K 1/20W 5% 0201; Chkd/date: PRAVEEN/080922; Crtd /date: TAMILARASU/080922; Custom_Duty: 15%; Customs_HS_Code: 85332119; Distributor_name: DIGIKEY; Distributor_part_number: P123223CT-ND; Footprint Path: Y:\MIS_DATABASE\Library\ALTIUM_TOOL\PCB_FOOTPRINTS\Altium_Footprint_Lib.PcbLib; Height: 0.26MM; Library Path: Y:\MIS_DATABASE\Library\ALTIUM_TOOL\SCHEMATICS_PARTS\MS_DISCRETE_Library.schlib; Mfr_name: PANASONIC-ECG; Mfr_part_number: ERJ-1GNJ104C; Mistral Part No: 110022090005-R; Package: 0201; Part_type: RESISTORS\FIXED; Project: SK AM62Q LP EVM BRD; RoHS: RoHS; Temperature: -55°C+125°C; Tolerance: 5%; Voltage: NA; Wattage: 1/20W; Weight: 0.15mg; Datasheet: Y:\MIS_DATABASE\DATASHEETS\RESISTORS\PAN-ERJSER_NOV17.PDF
U45 = TPS22946_DSBGA6: IC CURRENT-LIMITED LOAD SWITCH WITH SHUTOFF AUTO-RESTART AND OVERCURRENT CONDITION TIME-OUT DSBGA6; Chkd/date: MANIRAJA/220121; Crtd /date: ALVY/220121; Custom_Duty: 15%; Customs_HS_Code: 85423100; Distributor_name: DIGIKEY; Distributor_part_number: 296-25219-1-ND; Footprint Path: Y:\MIS_DATABASE\Library\ALTIUM_TOOL\PCB_FOOTPRINTS\Altium_Footprint_Lib.PcbLib; Height: 0.50MM; Library Path: Y:\MIS_DATABASE\Library\ALTIUM_TOOL\SCHEMATICS_PARTS\MS_MISCPOWER_Library.schlib; Mfr_name: TEXAS INSTRUMENTS; Mistral Part No: 142021010016-R; Package: DSBGA6; Part_type: ICS\POWER\MANAGEMENT; Project: AM64X_SKEVM; RoHS: RoHS; Temperature: -40°C+85°C; Tolerance: NA; Voltage: NA; Wattage: NA; Weight: 1.7mg; Datasheet: Y:\MIS_DATABASE\DATASHEETS\ICS\POWER\TPS22946.PDF

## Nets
DGND: C53.2 C62.2 C185.2 C186.2 C187.2 C190.1 C191.2 C192.2 C195.1 C196.2 C380.2 C381.1 C384.2 C386.2 J3.6 J3.9 J3.14 J3.20 J3.25 J3.34 J11.2 R290.1 R293.1 R435.1 U45.B1(GND) U46.B1(GND) U65.B1(GND) ; also on sheet 1 2 3 4 13 14 15 16 17 18 19 20 21 22 23 24 25 26 27 28 29 30 31 34 35 36 37 38 39 40 41 42 43
VCC3V3_EXP: C192.1 C195.2 C196.1 J3.1 J3.17 R294.1 R295.1 R297.1 R298.1 R299.1 U46.A1(VOUT)
VCC3V3_PRU: C380.1 C381.2 C384.1 J11.1 R432.1 U65.A1(VOUT)
VCC5V0_EXP: C185.1 C190.2 C191.1 J3.2 J3.4 U45.A1(VOUT)
VCC_3V3_SYS: C186.1 C386.1 R589.2 U46.A2(VIN) U65.A2(VIN) ; also on sheet 1 4 15 16 19 20 21 23 24 26 27 29 30 31 34 36 37 38 39 40 41 42 43
VCC_5V0: C187.1 R288.2 R291.1 U45.A2(VIN) ; also on sheet 13 14 35 38 41
VDDSHV_CANUART: R80.1 ; also on sheet 2 4 17 31
AUDIO_EXT_REFCLK1: U12.C16(MCASP0_AFSX) ; also on sheet 41
BOOTMODE0: RA8.2 ; also on sheet 27
BOOTMODE1: RA8.4 ; also on sheet 27
BOOTMODE2: RA8.1 ; also on sheet 27
BOOTMODE3: RA8.3 ; also on sheet 27
BOOTMODE4: RA7.3 ; also on sheet 27
BOOTMODE5: RA7.2 ; also on sheet 27
BOOTMODE6: RA7.4 ; also on sheet 27
BOOTMODE7: RA7.1 ; also on sheet 27
BOOTMODE8: RA6.1 ; also on sheet 27
BOOTMODE9: RA6.2 ; also on sheet 27
BOOTMODE10: RA5.1 ; also on sheet 27
BOOTMODE11: RA5.4 ; also on sheet 27
BOOTMODE12: RA5.2 ; also on sheet 27
BOOTMODE13: RA5.3 ; also on sheet 27
BOOTMODE14: RA6.3 ; also on sheet 27
BOOTMODE15: RA6.4 ; also on sheet 27
CAN_FD_WKUP_HDR_INH: R82.1 ; also on sheet 34
CAN_FD_WKUP_SW_INH: R78.2 ; also on sheet 2
CPSW_RGMII_INTn/PRU_INTn: R433.1 ; also on sheet 24 42
ETH_CAN_INH: R76.2 R78.1 R79.2 R82.2
ETH_CAN_INH_PMIC: R76.1 ; also on sheet 4
ETH_CAN_INH_SOC: R79.1 R80.2 ; also on sheet 34
EXP_CLKOUT0: J3.7 ; also on sheet 42
EXP_EHRPWM1_B: J3.33 U12.D18(MCASP0_AXR0)
EXP_GPIO0_14: J3.22 ; also on sheet 34
EXP_GPIO0_32: J3.30 RA4.5
EXP_GPIO0_33: J3.31 U12.K21(GPMC0_OEN_REN)
EXP_GPIO0_36: J3.29 U12.K18(GPMC0_BE1N)
EXP_GPIO0_38: J3.16 U12.P17(GPMC0_WAIT1)
EXP_GPIO0_39: J3.18 U12.J20(GPMC0_WPN)
EXP_GPIO0_40/PR0_ECAP0_IN_APWM_OUT: J3.32 U12.J19(GPMC0_DIR)
EXP_GPIO0_41: J3.37 U12.J18(GPMC0_CSN0)
EXP_GPIO0_42: J3.13 U12.H17(GPMC0_CSN1)
EXP_GPIO1_22: J3.15 ; also on sheet 42
EXP_HAT_DETECT: J3.39 ; also on sheet 39
EXP_I2C2_SCL: J3.5 ; also on sheet 38
EXP_I2C2_SDA: J3.3 ; also on sheet 38
EXP_PS_3V3_EN: R293.2 U46.B2(ON) ; also on sheet 39
EXP_PS_5V0_EN: R290.2 U45.C2(ON) ; also on sheet 39
EXP_SPI0_CLK: J3.23 ; also on sheet 42
EXP_SPI0_CS0: J3.24 R299.2 ; also on sheet 42
EXP_SPI0_CS1: J3.26 R298.2 ; also on sheet 42
EXP_SPI0_D0: J3.19 ; also on sheet 42
EXP_SPI0_D1: J3.21 ; also on sheet 42
EXP_SPI2_CLK: J3.40 ; also on sheet 37
EXP_SPI2_CS0/EHRPWM0_A: J3.12 R294.2 ; also on sheet 37
EXP_SPI2_CS1: J3.11 R295.2 U12.C17(MCASP0_ACLKX)
EXP_SPI2_CS2: J3.36 R297.2 U12.A18(MCASP0_AXR1)
EXP_SPI2_D0: J3.38 ; also on sheet 37
EXP_SPI2_D1/ECAP2_IN_APWM_OUT: J3.35 ; also on sheet 37
EXP_UART5_RXD: J3.10 ; also on sheet 42
EXP_UART5_TXD: J3.8 ; also on sheet 42
HFOSC0_CLKOUT_32K: U12.B12(WKUP_CLKOUT0) ; also on sheet 19
MCASP1_ACLKX: RA1.3 RA4.3 U12.K17(GPMC0_BE0N_CLE)
MCASP1_ACLKX_BUF: RA1.6 ; also on sheet 39
MCASP1_AFSX: RA1.2 RA4.2 U12.P21(GPMC0_WAIT0)
MCASP1_AFSX_BUF: RA1.7 ; also on sheet 39
MCASP1_AXR0: RA1.1 RA4.1 U12.J17(GPMC0_WEN)
MCASP1_AXR0_BUF: RA1.8 ; also on sheet 39
MCASP1_AXR2: RA1.4 RA4.4 U12.K20(GPMC0_ADVN_ALE)
MCASP1_AXR2_BUF: RA1.5 ; also on sheet 39
MCU_RESETSTATz: R420.1 ; also on sheet 34 42
PMIC_MODE: TP25.1(TP) U12.C7(PMIC_LPM_EN0) ; also on sheet 4
PR0_PRU0_GPO0: J11.13 RA8.7 U12.K19(GPMC0_AD0)
PR0_PRU0_GPO1: J11.14 RA8.5 U12.L19(GPMC0_AD1)
PR0_PRU0_GPO2: J11.15 RA8.8 U12.L20(GPMC0_AD2)
PR0_PRU0_GPO3: J11.16 RA8.6 U12.L21(GPMC0_AD3)
PR0_PRU0_GPO4: J11.17 RA7.6 U12.M21(GPMC0_AD4)
PR0_PRU0_GPO5: J11.18 RA7.7 U12.L17(GPMC0_AD5)
PR0_PRU0_GPO6: J11.19 RA7.5 U12.L18(GPMC0_AD6)
PR0_PRU0_GPO7: J11.20 RA7.8 U12.M20(GPMC0_AD7)
PR0_PRU0_GPO11: J11.7 RA4.8
PR0_PRU0_GPO12: J11.9 RA4.7
PR0_PRU0_GPO14: J11.11 RA4.6
PRU_3V3_EN: R435.2 R589.1 U65.B2(ON) ; also on sheet 39
PRU_DETECT: J11.3 ; also on sheet 39
PRU_INTn: J11.5 R432.2 R433.2
PRU_RESETz: J11.4 R420.2 R421.2
RESETSTATz: R421.1 ; also on sheet 1 4 20 21 22 24 27 37 38 39 40 41 42
SoC_I2C0_SCL: J3.28 J11.6 ; also on sheet 4 13 23 37 42
SoC_I2C0_SDA: J3.27 J11.8 ; also on sheet 4 13 23 37 42
SoC_I2C2_SCL: U12.H18(GPMC0_CSN2) ; also on sheet 38
SoC_I2C2_SDA: U12.H19(GPMC0_CSN3) ; also on sheet 38
SoC_RGMII_MDC: U12.V17(MDIO0_MDC) ; also on sheet 1 24
SoC_RGMII_MDIO: U12.U16(MDIO0_MDIO) ; also on sheet 1 24
SOC_SPI2_CLK: U12.D16(MCASP0_ACLKR) ; also on sheet 37
SOC_SPI2_CS0: U12.D15(MCASP0_AFSR) ; also on sheet 37
SOC_SPI2_D0: U12.B18(MCASP0_AXR3) ; also on sheet 37
SOC_SPI2_D1: U12.B17(MCASP0_AXR2) ; also on sheet 37
SoC_VOUT0_DATA16: RA6.8 U12.N20(GPMC0_AD8) ; also on sheet 41
SoC_VOUT0_DATA17: RA6.7 U12.N21(GPMC0_AD9) ; also on sheet 41
SoC_VOUT0_DATA18: RA5.8 U12.M17(GPMC0_AD10) ; also on sheet 41
SoC_VOUT0_DATA19: RA5.5 U12.N18(GPMC0_AD11) ; also on sheet 41
SoC_VOUT0_DATA20: RA5.7 U12.N17(GPMC0_AD12) ; also on sheet 41
SoC_VOUT0_DATA21: RA5.6 U12.N19(GPMC0_AD13) ; also on sheet 41
SoC_VOUT0_DATA22: RA6.6 U12.P19(GPMC0_AD14) ; also on sheet 41
SoC_VOUT0_DATA23: RA6.5 U12.P20(GPMC0_AD15) ; also on sheet 41
VSEL_SD_SOC: U12.M19(GPMC0_CLK) ; also on sheet 4
WKUP_LFOSCO_XI: C62.1 U12.A2(WKUP_LFOSC0_XI) Y2.1
WKUP_LFOSCO_XO: C53.1 U12.A3(WKUP_LFOSC0_XO) Y2.2
WKUP_UART0_CTS_3V3: U12.A7(WKUP_UART0_CTSN) ; also on sheet 31
WKUP_UART0_RTS_3V3: U12.B4(WKUP_UART0_RTSN) ; also on sheet 31
WKUP_UART0_RX_3V3: U12.B5(WKUP_UART0_RXD) ; also on sheet 31
WKUP_UART0_TX_3V3: U12.C6(WKUP_UART0_TXD) ; also on sheet 31
N16931396: R291.2 U45.B2(CL)
N16931420: R288.1 U45.C1(OC)

Not connected (* = marked no-connect by the designer): J11 10* 12*; U12 A9(WKUP_I2C0_SDA) E9(WKUP_I2C0_SCL)

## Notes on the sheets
sheet 32
- SOC WKUP DOMAIN
- D-Note :-
  A pullup is recommended for Open
  drain output type I2C interfaces
  irrespective of the IO configuration
  Refer pin connectivity table of SOC
  data sheet
- D-Note :-
  Open-drain output type buffer I2C interfaces
  have slew rate requirement when pulled to 3.3 V.
  An RC is recommended for slew rate control
  Refer SK-AM62P-LP schematics
- Note: R1384, R1385 are
  Tripad
- D-Note :-
  WKUP LFOSC0 has limited use case. Provide provision to ground Xi when not used. Refer SOC data sheet
- D-Note :-
  WKUP_CLKOUT0 is a buffered output of
  the high frequency oscillator (HFOSC0)
  available during power-up as default
- ECS-.327-9-34QCS-TR
- D-Note :-
  The only LFOSC0 register bits that should be changed by the customer are BP_C, PD_C, and
  CTRLMMR_WKUP_LFXOSC_TRIM[18:16], where PD_C is reset (0) to enable the oscillator and the BP_C bit is only set (1) to
  place the oscillator in bypass mode when using an LVCMOS clock source.The CTRLMMR_WKUP_LFXOSC_TRIM[18:16] bits are set
  based on the actual capacitance load applied to the crystal, as defined by the Load Capacitance Equation. The load
  capacitance range of the crystal will be half of the recommended capacitor value range since there are connected in
  series with the crystals resonate circuit.
- D-Note :-
  Refer SoC data sheet for the recommended circuit configuration
  during preproduction PCB and the production PCB
- SOC GPMC INTERFACE
- D-Note :-
  Shorting of bootmode inputs (IOs) is not recommended or allowed since the IOs
  have alternate functions that could be configured after boot
  Shorting the bootmode pins directly to VCC or ground directly is not recommended
  Connect each of the bootmode pins through separate resistor
  Choose the bootmode resistor value based on the use case (10K or similar)
- D-Note
  Add a series resistor 0R when used as GPMC0_CLK
- D-Note :-
  SOC IO buffers for signals used for GPMC interface
  are disabled during reset
  The required pulls for the interfaced signals are
  provided on the GPMC interface card
- @ GPMC0_AD8- AD15
  > HDMI 16 to 23 bits
- D-Note :-
  When bootmode Isolation buffers are not used,
  connect the bootmode configuration resistors
  directly to the SOC bootmode input pins.
  Connect the SOC bootmode signal used for
  alternate function to the attached device
  through 0R for isolation or testing.
- D-Note :-
  Delete or reduce the series resistor value  to 0R when buffers are not used,
  These resistors could be used to isolate the alternate function during testing
- GPIO_43
- GPIO_44
- BOOTMODE PINS
- D-Note :-
  Add a 22R at the
  output of MCASP1_ACLKX
  near to the SOC
- MCASP1_AXR2
- MCASP1_ACLKX
- Cad Note: Place such that stubs
  are minimum.  use TRIPAD ACTION
- GPIO0_40
- MCASP1_AFSX
- MCASP1_AXR0
- MCASP1_ACLKX
- MCASP1_AFSX
- MCASP1_AXR2
- MCASP1_AXR0
- MCASP1_AXR0
- MCASP1_ACLKX
- MCASP1_AFSX
- To PRU connector
  for x8 NAND Interface
- MCASP1_AXR2
- TO RI-pi or User Exp hdr
- POWER SWITCH FOR PRU HEADER
- R-Note :-  Resistors are used to
  isolate the BOOTMODE control logic
  after the value is latched
- HDMI
- McASP1
- MUX
- AUDIO
- DNI
- PRU HEADER
- M.2 Wilink BT
- BUF
- x8 NAND (PRU HDR)
- 4
- D-Note :-
  Can support custom design
  to source 500mA
- 3V3 supply of PRU Header is limited to sourcing 500mA max.
- MCASP1_AXR0
- For x8 NAND Interface
- MCASP1_ACLKX
- MCASP1_AFSX
- D-Note :-
  Any SoC IO that has a trace connected but not being driven
  actively needs to be connected to an external pull.
  When adding pull is not feasible, ensure the traces are
  routed away from noisy signals
- Silk: PRU HDR
- D-Note:- Processor IOs connected to PRU Header are not fail-safe.
  No external input shall be driven when Starter Kit is not powered-up.
sheet 33
- USER EXPANSION CONNECTOR
- R-Note :-
  These supplies are off by default
  The supplies are controlled by the below
  load switches and needs to be enabled
- GPIO1_10
- GPIO1_9
- GPIO1_7
- GPIO1_8
- D-Note:-
  Add a series resistor 22R on the
  SPI clock output signal near to the SoC
- GPIO1_14
- Note: Expansion boards should take care
  of the null modem connectivity for the
  UART signals (cross-over of Rx and Tx)
- GPIO1_13
- D-Note:- Processor IOs connected to USER
  EXPANSION CONNECTOR are not fail-safe.
  No external input shall be applied when
  Starter Kit is not powered-up.
- SoC_I2C2_SCL
- SoC_I2C2_SDA
- GPIO0_43
- GPIO0_44
- GPIO1_30
- GPIO1_24
- GPIO1_25
- GPIO1_11
- GPIO1_13
- GPIO0_42
- GPIO1_22
- GPIO0_38
- GPIO1_18
- GPIO0_39
- GPIO1_19
- GPIO0_14
- GPIO1_17
- GPIO1_15
- GPIO1_16
- GPIO1_27
- GPIO1_26
- GPIO0_33
- GPIO0_36
- GPIO0_32
- GPIO0_40
- MCASP1_AXR2
- GPIO1_10
- GPIO1_8
- GPIO1_9
- GPIO0_41
- GPIO1_7
- GPIO1_14
- Silk: USER EXPN
- LOAD SWITCHES FOR USER EXPANSION CONNECTOR
- D-NOTE :-
- AM62x Starter Kit shall not be powered through the 5V0 or 3V3 pins on the 40-pin User Expansion
  Connector.
  User Expansion Connector I/O are not fail-safe and shall not be driven when AM62x Starter Kit is
  not powered.
  5V supply of User Expansion Connector is limited to sourcing 155mA max.
  3V3 supply of User Expansion Connector is limited to sourcing 500mA max.
- It should be connected to PORz of the SoC TBD
